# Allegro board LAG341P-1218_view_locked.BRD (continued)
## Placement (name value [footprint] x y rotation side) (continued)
PR805  -  [R_0402]  108.51 133.57 270 bottom
PR806  -  [R_0402]  109.4 133.57 270 bottom
PR807  -  [R_0402]  108.46 131.84 180 bottom
PR808  -  [R_0402]  110.21 132.73 0 bottom
PR809  -  [R_0402]  102.67 129.35 90 bottom
PR818  -  [R_0402]  109.91 128.34 90 bottom
PR819  -  [R_0402]  101.9 130.27 270 bottom
PR838  -  [R0402_0OHM]  105 130.32 0 top
PR839  -  [R_0402]  105 128.8 0 top
PR840  -  [R_0402]  103.56 130.14 270 top
PR841  -  [R0402_0OHM]  105 129.56 0 top
PR900  -  [R0402_0OHM]  237.74 183.28 180 top
PR901  -  [R_1206]  230.37 182.26 0 top
PR902  -  [R0402_0OHM]  243.89 180.31 270 bottom
PR903  -  [R0402_0OHM]  243.13 178.66 270 bottom
PR904  -  [R_0402]  238.18 177.74 90 top
PR905  -  [R_0402]  243.13 180.31 270 bottom
PR906  -  [R_0402]  241.3 178.66 270 bottom
PR907  -  [R_0402]  243.89 177.74 90 bottom
PR908  -  [R_0402]  239.01 178.66 270 bottom
PR909  -  [R_0402]  240.54 177.74 90 bottom
PR910  -  [R0402_0OHM]  239.78 178.66 270 bottom
PR951  -  [R_0402]  244.91 182.65 180 top
PR952  -  [R0402_0OHM]  242.34 182.65 0 top
PR1000  -  [R_0402]  162 183.78 0 bottom
PR1001  -  [R_0402]  162.6 182.98 180 bottom
PR1002  -  [R_0402]  162.9 183.09 180 top
PR1003  -  [R0402_0OHM]  162.09 184.56 0 bottom
PR1004  -  [R_0402]  162.31 181.52 180 bottom
PR1005  -  [R_0402]  167.39 185.27 90 bottom
PR1006  -  [R_0402]  164.05 185.32 90 bottom
PR1007  -  [R_0402]  163.28 186.24 270 bottom
PR1008  -  [R_0402]  164.81 185.32 90 bottom
PR1009  -  [R_1206]  188.77 191.58 180 top
PR1010  -  [R_0603]  161.72 180.61 270 bottom
PR1011  -  [R_0402]  160.96 187.55 270 top
PR1012  -  [R_0603]  163.36 196.31 270 bottom
PR1013  -  [R_0402]  168.24 186.11 270 bottom
PR1014  -  [R_0402]  170.81 185.37 180 bottom
PR1015  -  [R_0603]  168.12 184.57 90 top
PR1016  -  [R_0402]  176.79 177.06 180 top
PR1017  -  [R0402_0OHM]  169.68 179.94 0 bottom
PR1018  -  [R0402_0OHM]  170.47 183.9 180 bottom
PR1019  -  [R_0402]  169.68 180.7 0 bottom
PR1020  -  [R_1206]  172.75 180.79 90 top
PR1021  -  [R0402_0OHM]  170.47 183.14 180 bottom
PR1022  -  [R_0402]  169.68 181.46 0 bottom
PR1023  -  [R_0402]  176.79 177.82 180 top
PR1100  -  [R_0402]  112.01 167.15 180 top
PR1101  -  [R_0603]  111.18 166.07 270 bottom
PR1103  -  [R_0402]  113.84 167.71 90 top
PR1104  -  [R_0402]  105.84 167.84 90 top
PR1105  -  [R_0402]  106.73 168.75 270 top
PR1106  -  [R_0402]  107.75 167.84 90 top
PR1107  -  [R_0402]  108.64 167.84 90 top
PR1108  -  [R0402_0OHM]  118.03 168.37 270 top
PR1109  -  [R_0402]  116.2 168.42 180 top
PR1110  -  [R0402_0OHM]  118.03 169.23 90 top
PR1111  -  [R_0402]  116.2 169.31 180 top
PR1112  -  [R_0402]  109.88 173.18 270 bottom
PR1113  -  [R_0402]  106.22 171.04 270 top
PR1115  -  [R_0402]  117.02 169.23 90 top
PR1116  -  [R_0402]  108.89 171.04 270 top
PR1117  -  [R_0402]  110.67 169.36 90 top
PR1118  -  [R0402_0OHM]  108 171.04 270 top
PR1119  -  [R_0402]  111.66 173.18 270 bottom
PR1120  -  [R_0402]  107.11 171.04 270 top
PR1122  -  [R_0402]  115.19 172.57 270 bottom
PR1123  -  [R_0402]  109.05 172.27 90 bottom
PR1124  -  [R0402_0OHM]  118.24 171.09 180 top
PR1125  -  [R0402_0OHM]  109.78 170.53 270 top
PR1126  -  [R0402_0OHM]  118.24 171.98 180 top
PR1127  -  [R_0402]  117.22 172.87 180 top
PR1130  -  [R0402_0OHM]  105.28 171.85 180 bottom
PR1131  -  [R_0402]  105.28 174.52 180 bottom
PR1132  -  [R0402_0OHM]  103.43 173.45 270 bottom
PR1134  -  [R_0402]  118.8 174.72 270 top
PR1135  -  [R_0402]  113.64 174.77 0 bottom
PR1136  -  [R_0402]  117.96 175.53 0 top
PR1137  -  [R_0402]  118.03 174.72 270 top
PR1138  -  [R_0402]  105.21 172.94 270 top
PR1139  -  [R_0402]  106.53 175.28 0 bottom
PR1140  -  [R_0402]  104.37 173.75 0 top
PR1141  -  [R_0402]  104.27 174.52 180 top
PR1142  -  [R_0402]  117.09 175.66 180 top
PR1143  -  [R_0402]  105.14 176.28 180 top
PR1144  -  [R_0402]  119.18 176.47 90 top
PR1145  -  [R_0402]  103.43 176.22 90 top
PR1146  -  [R_0402]  106.86 181.2 270 top
PR1147  -  [R_0603]  120.38 179.6 180 bottom
PR1148  -  [R_0402]  118.36 178.2 180 top
PR1149  -  [R_0402]  103.43 177.87 90 top
PR1150  -  [R_0603]  120.38 178.33 180 bottom
PR1151  -  [R_0603]  102.92 180.04 90 top
PR1152  -  [R_0603]  120.76 175.79 180 bottom
PR1153  -  [R_0402]  106.05 181.76 180 top
PR1154  -  [R_0402]  115.32 181.76 180 top
PR1155  -  [R_0603]  120.76 177.06 180 bottom
PR1156  -  [R_0603]  111.18 182.83 270 top
PR1157  -  [R_0402]  106.73 179.67 270 bottom
PR1158  -  [R_0402]  107.62 179.67 270 bottom
PR1159  -  [R_0402]  120.4 180.61 180 bottom
PR1160  -  [R_0402]  116.51 179.39 90 bottom
PR1161  -  [R_0402]  112.45 180.69 270 bottom
PR1162  -  [R_0402]  111.18 179.67 270 bottom
PR1163  -  [R_0402]  110.29 179.67 270 bottom
PR1164  -  [R_0402]  109.4 179.67 270 bottom
PR1165  -  [R_0402]  108.51 179.67 270 bottom
PR1166  -  [R_0402]  103.94 180.66 90 top
PR1167  -  [R_0402]  120.4 181.5 180 bottom
PR1168  -  [R_0402]  113.26 181.25 0 bottom
PR1169  -  [R_0402]  119.76 174.77 180 bottom
PR1170  -  [R_0402]  114.55 177.31 180 bottom
PR1171  -  [R_0402]  120.27 178.2 180 top
PR1172  -  [R0402_0OHM]  116.43 180.36 0 top
PR1173  -  [R0402_0OHM]  106.86 185.11 90 top
PR1174  -  [R_0402]  105.13 183.53 0 top
PR1175  -  [R_0402]  117.35 179.47 180 top
PR1176  -  [R_0402]  106.05 186.07 180 top
PR1200  -  [R_0603]  129.84 185.5 90 top
PR1201  -  [R_0603]  130.73 186.2 0 bottom
PR1202  -  [R_0402]  134.49 172.99 180 top
PR1203  -  [R_1206]  135.37 177.95 0 top
PR1204  -  [R_0603]  139.24 187.41 270 bottom
PR1205  -  [R_0603]  141.78 186.01 90 bottom
PR1206  -  [R_0402]  142.11 172.61 180 top
PR1207  -  [R_1206]  142.99 177.95 0 top
PR1251  -  [R_0603]  147.37 187.28 270 bottom
PR1252  -  [R_0603]  150.04 185.82 90 bottom
PR1253  -  [R_0402]  149.73 172.61 180 top
PR1254  -  [R_1206]  150.61 177.69 0 top
PR1255  -  [R_0603]  154.86 187.28 270 bottom
PR1256  -  [R_0603]  157.47 185.82 90 bottom
PR1257  -  [R_0402]  157.35 172.61 180 top
PR1258  -  [R_1206]  157.91 177.37 90 top
PR1500  -  [R_0402]  185.06 179.02 90 bottom
PR1501  -  [R_0402]  185.82 179.93 270 bottom
PR1502  -  [R_0402]  186.59 179.93 270 bottom
PR1503  -  [R0402_0OHM]  183.33 179.86 0 bottom
PR1505  -  [R_0402]  183.14 184.33 180 bottom
PR1507  -  [R_0402]  182.9 181.38 0 bottom
PR1508  -  [R_0402]  182.96 182.17 180 top
PR1509  -  [R_0402]  183.11 181.25 0 top
PR1510  -  [R_0603]  187.72 178.92 0 bottom
PR1511  -  [R_0402]  184.76 182.26 0 top
PR1512  -  [R_1206]  187.95 168.61 90 top
PR1513  -  [R_0603]  191.5 186.07 180 bottom
PR1514  -  [R_0402]  180.46 184.73 0 bottom
PR1515  -  [R_0402]  182.23 185.09 0 bottom
PR1516  -  [R_0402]  182.23 185.85 0 bottom
PR1517  -  [R0402_0OHM]  204.33 122.71 270 bottom
PR1518  -  [R0402_0OHM]  187.55 187.47 0 bottom
PR1519  -  [R_0402]  186.8 185.81 90 bottom
PR1520  -  [R0402_0OHM]  205.28 122.71 270 bottom
PR1521  -  [R_0402]  183.46 186.71 0 bottom
PR1522  -  [R_0402]  187.68 185.82 0 bottom
PR1600  -  [R0402_0OHM]  240.74 170.81 270 bottom
PR1601  -  [R_1206]  239.06 168.74 270 bottom
PR1602  -  [R0402_0OHM]  247.52 174.64 180 bottom
PR1603  -  [R_0402]  246.56 167.21 0 bottom
PR1604  -  [R_0402]  246.61 173.88 0 bottom
PR1605  -  [R_0402]  247.53 169.03 270 bottom
PR1606  -  [R_0402]  247.27 171.35 180 bottom
PR1607  -  [R0402_0OHM]  246.35 170.59 0 bottom
PR1608  -  [R_0402]  246.3 169.82 0 bottom
PR1643  -  [R_0402]  245.67 173.17 90 top
PR1651  -  [R0402_0OHM]  246.43 174.08 270 top
PR1700  -  [R_0603]  111.43 135.84 270 bottom
PR1701  -  [R_0603]  108.64 135.84 270 bottom
PR1702  -  [R_0402]  109.27 147.77 90 top
PR1703  -  [R_1206]  106.29 144.54 180 top
PR1704  -  [R_0603]  102.67 162.13 90 bottom
PR1705  -  [R_0603]  106.73 163.91 90 bottom
PR1706  -  [R_1206]  107.18 155.72 0 top
PR1800  -  [R_0402]  176.62 81.4 180 top
PR1801  -  [R0402_0OHM]  179.37 75.84 180 top
PR1803  -  [R_0402]  178.51 82.42 180 top
PR1804  -  [R_0402]  176.71 83.3 270 top
PR1805  -  [R_0603]  179.13 84.41 180 top
PR1851  -  [R0402_0OHM]  176.61 80.54 180 top
PR1900  -  [R_1206_4P-D]  54.91 78.52 270 bottom
PR1901  -  [R_0603]  47.42 75.27 90 top
PR1902  -  [R_0603]  44.37 75.39 90 top
PR1903  -  [R0603_0OHM]  49.9 76.6 180 top
PR1904  -  [R_0402]  52.88 79.32 90 bottom
PR1905  -  [R_0603]  43.1 75.39 90 top
PR1906  -  [R_0402]  52.12 80.23 270 bottom
PR1907  -  [R_0805]  51.61 80.23 0 top
PR1908  -  [R_0402]  40.39 77.74 180 top
PR1909  -  [R0402_0OHM]  52.64 82.38 180 top
PR1910  -  [R_1206_4P-D]  29.21 90.95 180 bottom
PR1911  -  [R_0402]  53.53 87.46 180 top
PR1912  -  [R_0402]  50.9 81.55 90 top
PR1913  -  [R0402_0OHM]  52.64 83.2 180 top
PR1914  -  [R_0603]  39.87 80.41 0 top
PR1915  -  [R_1206]  38.28 71.65 180 top
PR1916  -  [R_1206]  34.02 81.23 180 top
PR1917  -  [R0402_0OHM]  52.64 83.97 180 top
PR1918  -  [R_0402]  52.88 88.65 90 top
PR1919  -  [R0402_0OHM]  52.64 84.73 180 top
PR1920  -  [R_0402]  54.53 90.91 180 top
PR1921  -  [R0402_0OHM]  52.64 85.49 180 top
PR1922  -  [R0402_0OHM]  41.11 82.32 0 top
PR1923  -  [R_0402]  50.46 87.33 0 top
PR1924  -  [R_0402]  49.64 87.34 270 top
PR1925  -  [R_0402]  47.36 86.43 90 top
PR1926  -  [R_0402]  48.88 87.34 270 top
PR1927  -  [R_0402]  45.35 85.65 180 top
PR1928  -  [R0402_0OHM]  48.12 87.34 270 top
PR1929  -  [R0402_0OHM]  41.33 87.14 90 top
PR1930  -  [R0402_0OHM]  45.59 86.44 0 top
PR1931  -  [R_0402]  40.13 83.46 180 top
PR1932  -  [R0402_0OHM]  43.87 87.19 90 top
PR1933  -  [R0402_0OHM]  44.69 87.19 90 top
PR1934  -  [R_0402]  42.15 87.19 90 top
PR1935  -  [R_0402]  40.13 84.22 180 top
PR1936  -  [R_0402]  58.98 80.79 90 top
PR1937  -  [R0402_0OHM]  61.16 75.54 0 top
PR1938  -  [R_0402]  39.54 87.9 0 top
PR1939  -  [R0402_0OHM]  59 75.66 0 top
PR1940  -  [R0402_0OHM]  61.44 83.08 0 top
PR1941  -  [R0402_0OHM]  62.19 78.99 180 top
PR1942  -  [R_0402]  62.34 82.33 270 top
PR1943  -  [R_0402]  62.13 77.46 270 top
PR1950  -  [R0402_0OHM]  135.65 68.24 180 bottom
PT201  -  [TPC12]  174.6 79.74 0 top
PT202  -  [TPC12]  22.42 76.66 0 top
PU200  -  [LM393DGKR_VSSOP8]  28.52 69.82 180 top
PU201  -  [TC7SH08FU_SSOP5]  15.86 100.36 270 bottom
PU202  -  [TC7SH08FU_SSOP5]  20.23 84.29 0 top
PU203  -  [LM393DGKR_VSSOP8]  21.02 73.85 180 top
PU204  -  [RT9069-33GB_SOT23-5]  65.96 94.76 315 top
PU400  -  [TPS51285BRUKR_QFN20_3X3]  343.71 86.7 180 top
PU500  -  [SY8288RAC_QFN20_3X3]  130.41 75.14 270 bottom
PU600  -  [G5616ARZ1U_TQFN20_3X3]  285.23 98.32 0 bottom
PU700  -  [RT8812AGQW_WQFN20_3X3-S]  193.24 182.86 90 top
PU800  -  [NB681AGD-Z_QFN13_2X3-SVR]  105.98 130.24 270 bottom
PU900  -  [SY8286RAC_QFN20_3X3]  238.42 183.18 270 bottom
PU1001  -  [RT8816AGQW_WQFN20_3X3]  164.34 181.55 90 bottom
PU1100  -  [NCP81215MNTXG_QFN52_6X6]  113.49 173.51 180 top
PU1200  -  [NCP302035MNTXG_PQFN33_5X5]  129.75 184.79 0 bottom
PU1201  -  [NCP302035MNTXG_PQFN33_5X5]  138.76 184.79 0 bottom
PU1251  -  [NCP302035MNTXG_PQFN33_5X5]  147.65 184.6 0 bottom
PU1252  -  [NCP302035MNTXG_PQFN33_5X5]  155.08 184.6 0 bottom
PU1501  -  [RT8816AGQW_WQFN20_3X3]  187.46 181.43 180 bottom
PU1600  -  [SY8286RAC_QFN20_3X3]  241.99 170.54 0 bottom
PU1700  -  [NCP302035MNTXG_PQFN33_5X5]  109.5 137.44 180 bottom
PU1701  -  [NCP302035MNTXG_PQFN33_5X5]  104.85 162.69 0 bottom
PU1800  -  [RT9059GQW_WDFN10_3X3]  179.79 81.06 180 top
PU1900  -  [ISL88738HRTZ-T_TQFN32_4X4]  44.63 83.2 0 top
PU1901  -  [TC7SH08FU_SSOP5]  60.04 80.16 0 top
Q4  -  [L2N7002WT1G_SC-70-3]  339.27 170.51 0 top
Q5  -  [DMN66D0LDW-7_SOT363-6]  272.79 93 270 top
Q6  -  [L2N7002WT1G_SC-70-3]  308.66 102.44 180 bottom
QE2  -  [DMN65D8LDW-7_SOT363-6]  193.98 78.02 0 top
QE4  -  [DMN65D8LDW-7_SOT363-6]  284.72 70.49 90 top
QE5  -  [MMBT3904WH_SOT323-3]  172.56 184.34 0 bottom
QE6  -  [MMBT3904WH_SOT323-3]  187.17 118.16 0 top
QE7  -  [MMBT3904WH_SOT323-3]  110.63 182.9 270 bottom
QE8  -  [MMBT3904WH_SOT323-3]  177.59 116.73 180 bottom
QE9  -  [MMBT3904WH_SOT323-3]  238.87 174.57 0 bottom
QE10  -  [MMBT3904WH_SOT323-3]  298.18 71.81 0 top
QE11  -  [MMBT3904WH_SOT323-3]  27.36 115.93 90 bottom
QE12  -  [MMBT3904WH_SOT323-3]  279.2 95.31 180 bottom
QE13  -  [L2N7002WT1G_SC-70-3]  186.31 74.4 180 top
QE15  -  [MMBT3904WH_SOT323-3]  156.43 136.53 180 top
QE18  -  [DMN65D8LDW-7_SOT363-6]  284.72 73.41 90 top
QE20  -  [L2N7002WT1G_SC-70-3]  136.89 81.17 270 top
QF1  -  [DMN65D8LDW-7_SOT363-6]  231.76 110.9 270 top
QH1  -  [LP2301ALT1G_SOT23-3]  139.62 79.14 0 top
QH3  -  [2N7002KDW_SOT363-6]  345.99 150.85 0 top
QH4  -  [DMN65D8LDW-7_SOT363-6]  108.19 77.5 270 bottom
QH5  -  [2N7002KDW_SOT363-6]  344.78 153.02 180 top
QI10  -  [L2N7002WT1G_SC-70-3]  324.66 111.34 180 top
QR1  -  [L2N7002WT1G_SC-70-3]  346 99.39 180 bottom
QR104  -  [L2N7002WT1G_SC-70-3]  174.68 76.47 0 top
QR105  -  [L2N7002WT1G_SC-70-3]  331.01 109.43 0 bottom
QRTC  -  [LP2301ALT1G_SOT23-3]  169.21 73.55 270 top
QRTC1  -  [DMN65D8LW-7_SOT323-3]  176.46 71.22 90 top
QV3  -  [DMN65D8LDW-7_SOT363-6]  246.86 113.69 0 top
QV11  -  [SI3457BDV-T1-E3_TSOP6]  43.85 101.18 180 top
QV12  -  [L2N7002WT1G_SC-70-3]  37.07 100.83 270 top
QV21  -  [DMN63D8LDW-7_SOT363-6]  199.51 112.96 180 top
QV89  -  [L2N7002WT1G_SC-70-3]  24.18 118.83 180 top
QV91  -  [2N7002W-T-R7_SOT323-3]  214.41 109.91 270 top
QV98  -  [2N7002W-T-R7_SOT323-3]  241.83 116.24 180 top
QV101  -  [2N7002W-T-R7_SOT323-3]  217.89 173.93 90 top
QV102  -  [2N7002W-T-R7_SOT323-3]  242.49 160.19 90 top
QV103  -  [2N7002W-T-R7_SOT323-3]  196.39 116.44 0 top
QV105  -  [2N7002W-T-R7_SOT323-3]  227.71 111.04 180 top
QZ6  -  [DMN65D8LDW-7_SOT363-6]  249.34 120.23 0 top
QZ9  -  [DMG2301U-7_SOT23-3]  51.87 92.63 0 bottom
QZ14  -  [DMN65D8LDW-7_SOT363-6]  220.95 184.93 90 top
QZ15  -  [DMN65D8LDW-7_SOT363-6]  164.35 184.09 0 top
QZ17  -  [DMN65D8LDW-7_SOT363-6]  249.86 109.75 0 top
QZ18  -  [L2N7002WT1G_SC-70-3]  219.38 180.3 180 top
R3  -  [R_0402]  170.6 71.01 0 top
R276  -  [R_0201]  168.22 72.01 270 top
R277  -  [R_0201]  172.85 73.42 270 top
R281  -  [R_0603]  312.98 98.38 270 bottom
R5831  -  [R_0402]  310.11 86.76 0 top
R5832  -  [R_0402]  143.05 81.7 180 top
R5841  -  [R_0201]  317.68 104.58 270 bottom
R5842  -  [R_0402]  276.61 92.6 180 top
R5843  -  [R_0402]  271.83 91.64 90 top
RA2  -  [R0603_0OHM]  0.67 97.91 90 top
RA4  -  [R_0201]  0.58 95.26 180 top
RA6  -  [R_0201]  0.18 96.75 90 bottom
RA7  -  [R_0201]  0.58 94.67 180 top
RA12  -  [R_0201]  13.49 103.46 180 bottom
RA13  -  [R_0201]  4.84 99.93 0 bottom
RA14  -  [R_0201]  4.84 100.56 0 bottom
RA15  -  [R_0201]  8.94 99.85 90 bottom
RA16  -  [R_0201]  7.86 99.8 90 bottom
RA17  -  [R_0201]  1.8 95.74 90 bottom
RA18  -  [R0603_0OHM]  2.41 97.06 270 top
RA19  -  [R_0402]  7.75 112.1 180 top
RA20  -  [R_0402]  9.73 125.81 0 bottom
RA21  -  [R_0402]  8.38 125.81 180 bottom
RA27  -  [R_0402]  9.72 108.67 180 top
RA28  -  [R_0402]  11.62 112.03 180 top
RA29  -  [R_0402]  9.19 110.46 270 top
RA30  -  [R_0402]  7.86 110.46 270 top
RA31  -  [R_0402]  7.15 108.67 0 top
RA51  -  [R_0402]  11.92 116.12 0 top
RA52  -  [R_0402]  11.65 114.94 90 bottom
RA57  -  [R_0201]  0 95.83 0 top
RA68  -  [R_0201]  11.66 103.92 315 bottom
RA73  -  [R_0603]  3.15 106.77 0 top
RA74  -  [R0603_0OHM]  9.93 107.76 270 top
RA75  -  [R_0402]  8.52 112.12 0 top
RA82  -  [R_0201]  2.73 111.94 180 bottom
RA93  -  [R_0402]  2.34 97.1 90 bottom
RA94  -  [R0402_0OHM]  0.13 98.37 90 bottom
RA95  -  [R_0402]  0.69 126.48 270 bottom
RA96  -  [R_0201]  99.87 84.35 180 top
RA97  -  [R_0201]  99.87 84.93 180 top
RA98  -  [R_0201]  20.5 99.71 270 bottom
RA99  -  [R_0201]  20.5 97.86 90 bottom
RA100  -  [R_0402]  5.62 99.55 90 top
RA101  -  [R_0402]  7.51 99.97 180 top
RA102  -  [R_0402]  148.94 74.24 270 bottom
RA103  -  [R_0402]  145.99 76.15 270 bottom
RC183  -  [R_0402]  339.08 109.1 90 bottom
RC184  -  [R_0402]  339.9 109.1 90 bottom
RC5831  -  [R_0201]  111.48 75.96 0 top
RC5832  -  [R_0201]  111.43 77.62 0 top
RC5833  -  [R_0201]  111.48 78.38 0 top
RC5834  -  [R_0201]  111.48 76.73 0 top
RC5835  -  [R_0402]  343.13 112.51 270 bottom
RD1  -  [R_0402]  169.1 86.97 0 top
RD2  -  [R_0402]  171.37 92.36 0 top
RD3  -  [R_0402]  150.22 85.01 180 top
RD4  -  [R_0402]  246.57 86 90 top
RD5  -  [R0402_0OHM]  246.58 84.23 0 top
RD6  -  [R_0402]  226.06 83.56 180 top
RD7  -  [R_0402]  266.24 80.08 180 top
RD8  -  [R_0402]  265.28 76.47 0 top
RD9  -  [R_0402]  266.19 73.55 180 top
RD10  -  [R_0402]  254.04 71.14 0 bottom
RD28  -  [R0402_0OHM]  170.01 86.08 180 top
RD29  -  [R0402_0OHM]  173.88 91.41 0 top
RD30  -  [R0402_0OHM]  148.96 85.84 90 top
RD31  -  [R0402_0OHM]  132.09 84.22 0 top
RD35  -  [R_0402]  134.67 84.22 180 top
RD38  -  [R0402_0OHM]  245.48 86.24 180 top
RD39  -  [R_0402]  247.48 83.42 180 top
RD40  -  [R0402_0OHM]  225.15 84.37 0 top
RD58  -  [R0402_0OHM]  252.26 71.14 0 bottom
RD59  -  [R_0402]  265.28 75.52 0 top
RD100  -  [R_0402]  235.69 75.84 0 top
RD101  -  [R_0402]  265.4 87.65 0 top
RE3  -  [R_0402]  330.25 174.71 90 top
RE7  -  [R_0402]  189.42 78.25 180 top
RE9  -  [R_0402]  195.18 81.24 180 top
RE16  -  [R0603_0OHM]  279.27 83.32 0 top
RE19  -  [R_0402]  304.09 90.44 0 top
RE20  -  [R_0402]  293.8 92.47 90 top
RE21  -  [R_0402]  293.17 89.55 0 top
RE22  -  [R_0402]  304.27 77.74 0 top
RE23  -  [R_0402]  304.27 76.85 0 top
RE24  -  [R_0402]  191.82 81.04 180 bottom
RE25  -  [R_0402]  288.47 88.79 180 top
RE26  -  [R_0402]  189.15 81.04 0 bottom
RE27  -  [R_0402]  301.32 95.14 270 top
RE30  -  [R_0402]  307.19 86.51 0 top
RE31  -  [R_0402]  307.26 69.92 90 top
RE32  -  [R_0402]  308.17 76.98 180 top
RE33  -  [R_0402]  300.79 70.62 90 top
RE34  -  [R_0402]  285.22 82.82 0 top
RE35  -  [R_0402]  300.66 89.93 270 top
RE36  -  [R_0402]  286.13 84.85 180 top
RE38  -  [R_0402]  308.1 87.52 180 top
RE39  -  [R0402_0OHM]  308.1 88.54 180 top
RE41  -  [R_0402]  305.05 87.84 180 top
RE43  -  [R_0402]  291.36 71.65 270 top
RE44  -  [R_0402]  292.25 70.73 90 top
RE45  -  [R_0402]  305.05 87.01 180 top
RE48  -  [R_0402]  301.93 92.02 90 top
RE50  -  [R_0402]  287.83 71.63 0 top
RE51  -  [R0402_0OHM]  289.36 76.78 90 top
RE52  -  [R_0402]  286.51 71.77 180 top
RE54  -  [R_0402]  289.48 71.65 270 top
RE55  -  [R_0402]  308.15 74.44 180 top
RE56  -  [R_0402]  280.86 70.44 0 top
RE58  -  [R_0402]  286.13 86.89 180 top
RE59  -  [R_0402]  296.01 92.47 0 top
RE60  -  [R_0402]  310.95 95.32 90 top
RE61  -  [R_0402]  296.93 90.29 180 top
RE62  -  [R_0402]  292.67 100.16 180 top
RE63  -  [R_0402]  305.49 94.94 90 top
RE64  -  [R_0402]  304.6 94.07 270 top
RE65  -  [R_0402]  304.6 94.94 90 top
RE66  -  [R_0402]  300.38 73.36 90 top
RE67  -  [R_0402]  299.52 89.17 90 top
RE68  -  [R_0402]  298.12 92.98 270 top
RE69  -  [R_0402]  299.9 70.62 90 top
RE70  -  [R_0402]  299.01 92.98 270 top
RE71  -  [R_0402]  301.55 90.01 270 top
RE72  -  [R_0402]  293.81 73.44 90 top
RE81  -  [R_0201]  98.48 103.18 270 top
RE82  -  [R_0201]  95.72 101.25 90 top
RE83  -  [R_0201]  332 114.33 90 bottom
RE84  -  [R_0201]  334.45 116.27 0 bottom
RE86  -  [R_0201]  152.07 80.32 270 top
RE87  -  [R_0402]  186.77 77.44 180 top
RE89  -  [R_0402]  283.58 80.59 90 top
RE90  -  [R_0402]  281.85 80.6 0 top
RE94  -  [R_0402]  281.74 73.47 90 top
RE95  -  [R_0402]  284.73 75.9 180 top
RE96  -  [R_0402]  297.79 89.12 90 top
RE99  -  [R_0402]  294.94 89.1 90 top
RE100  -  [R_0201]  95.85 100.14 0 top
RE101  -  [R_0201]  331.91 117.92 0 bottom
RE104  -  [R0603_0OHM]  94.79 101.26 90 top
RE105  -  [R0603_0OHM]  333.48 116.26 90 bottom
RE108  -  [R0402_0OHM]  79.1 102.11 0 top
RE109  -  [R0402_0OHM]  79.1 102.88 0 top
RE110  -  [R_0402]  286.13 83.84 180 top
RE111  -  [R_0402]  307.26 80.28 0 top
RE112  -  [R0402_0OHM]  310.11 85.49 0 top
RE113  -  [R_0201]  147.1 70.88 0 top
RE114  -  [R_0201]  146.66 74.06 0 top
RE115  -  [R_0201]  146.41 76.73 0 top
RE116  -  [R0402_0OHM]  150.42 77.62 0 bottom
RE117  -  [R0402_0OHM]  150.42 76.73 0 bottom
RE122  -  [R0402_0OHM]  305.18 75.84 180 top
RE125  -  [R_0201]  153.16 70.12 180 top
RE126  -  [R_0402]  307.25 77.81 0 top
RE129  -  [R0603_0OHM]  157.34 78.5 180 top
RE133  -  [R0201_0OHM]  146.66 75.08 0 top
RE136  -  [R_0402]  281.74 75.84 0 top
RE137  -  [R_0402]  285.93 74.39 270 top
RE138  -  [R0402_0OHM]  186.3 72.67 270 top
RE139  -  [R0402_0OHM]  308.15 78.76 180 top
RE141  -  [R0603_0OHM]  149.81 72.19 0 bottom
RE142  -  [R_0402]  304.52 82.57 0 top
RE143  -  [R_0402]  175.44 73.55 180 top
RE145  -  [R_0402]  292.28 73.53 90 top
RE183  -  [R_0402]  303.52 74.39 270 top
RE255  -  [R_0402]  316.15 97.6 90 bottom
RE273  -  [R_0402]  318.95 98.37 90 bottom
RE274  -  [R_0402]  317.55 98.37 90 bottom
RE275  -  [R_0402]  329.23 110.97 270 bottom
RE283  -  [R_0402]  293.83 71.65 270 top
RE284  -  [R_0402]  293.04 71.65 270 top
RE285  -  [R_0402]  304.14 84.47 0 top
RE286  -  [R_0402]  304.22 78.63 0 top
RE287  -  [R0402_0OHM]  299.65 95.12 0 top
RE288  -  [R0402_0OHM]  300.16 95.95 0 top
RE290  -  [R_0402]  304.98 88.92 180 top
RE291  -  [R_0402]  100 74.44 180 bottom
RE292  -  [R_0402]  299.79 92.06 90 top
RE293  -  [R_0402]  290.75 74.44 270 top
RE294  -  [R_0402]  291.52 74.44 270 top
RE295  -  [R_0402]  287.05 80.13 90 top
RE296  -  [R_0402]  288.09 82.31 180 top
RE297  -  [R_0402]  304.19 92.22 0 top
RE298  -  [R_0402]  300.28 96.79 0 top
RE299  -  [R_0402]  301.94 96.89 270 top
RE300  -  [R_0402]  308.18 79.52 180 top
RE301  -  [R_0402]  276.25 79.01 90 top
RE303  -  [R_0402]  301.59 70.61 90 top
RE304  -  [R_0603]  279.2 79.55 0 top
RE305  -  [R0402_0OHM]  307.26 92.09 0 top
RE306  -  [R_0402]  307.22 91.3 0 top
RE307  -  [R_0402]  267.16 87.66 0 top
RE309  -  [R_0402]  150.28 75.3 0 bottom
RE310  -  [R_0402]  150.44 78.4 0 bottom
RE311  -  [R_0402]  293.05 73.53 90 top
RE313  -  [R0201_0OHM]  291.95 99.62 270 bottom
RE321  -  [R_0201]  88.02 81.07 270 top
RE322  -  [R_0402]  303.64 94.37 90 bottom
RE323  -  [R_0402]  303.64 96.14 90 bottom
RF1  -  [R0603_0OHM]  239.42 111.66 90 top
RF2  -  [R_0402]  230.7 110.64 270 top
RF3  -  [R_0402]  236.21 111.6 270 top
RF4  -  [R_0402]  236.11 112.92 180 top
RF5  -  [R_0402]  237.1 111.6 270 top
RH2  -  [R_0201]  74.21 68.92 90 top
RH5  -  [R_0402]  120.95 161.36 90 bottom
RH6  -  [R_0402]  74.57 71.32 90 top
RH8  -  [R0402_0OHM]  122.78 163.21 0 bottom
RH12  -  [R0402_0OHM]  116.95 162.59 270 bottom
RH24  -  [R_0201]  171.57 123.2 0 bottom
RH30  -  [R_0402]  174.82 153.53 90 top
RH42  -  [R_0402]  77.75 84.82 180 top
RH59  -  [R_0201]  132.54 141.81 0 bottom
RH67  -  [R_0402]  277.22 73.72 180 top
RH70  -  [R_0402]  68.12 72.28 0 bottom
RH71  -  [R_0402]  100.08 84.85 180 bottom
RH72  -  [R_0201]  100.51 84.35 90 top
RH74  -  [R_0201]  68.76 75.84 0 bottom
RH75  -  [R_0201]  71.11 78.92 270 top
RH77  -  [R_0402]  61.79 68.92 180 bottom
RH78  -  [R_0201]  64.59 76.35 0 top
RH82  -  [R_0402]  64.25 69.68 0 top
RH83  -  [R_0201]  68.68 72.28 0 top
RH84  -  [R_0201]  72.69 68.56 90 top
RH85  -  [R_0402]  81.71 76.14 90 top
RH91  -  [R_0201]  100.71 76.5 180 bottom
RH95  -  [R_0402]  100.46 78.48 180 bottom
RH96  -  [R0201_0OHM]  91.63 69.13 180 top
RH97  -  [R_0402]  117.1 159.11 0 bottom
RH98  -  [R_0402]  116.93 159.97 90 bottom
RH100  -  [R_0402]  116.09 160 90 bottom
RH108  -  [R_0201]  90.68 95.47 225 top
RH109  -  [R_0402]  99.85 90.75 0 bottom
RH110  -  [R_0201]  87.64 68.09 0 bottom
RH119  -  [R_0402]  106.1 70.81 90 top
RH120  -  [R_0402]  105.21 70.81 90 top
RH130  -  [R_0402]  83.81 74.81 180 top
RH133  -  [R0402_0OHM]  68.66 74.24 0 bottom
RH145  -  [R_0402]  178.42 147.41 315 bottom
RH146  -  [R_0201]  100.08 77.82 180 bottom
RH147  -  [R_0201]  103.09 77.79 180 bottom
RH148  -  [R_0201]  171.57 123.77 0 bottom
RH149  -  [R_0201]  171.57 124.36 0 bottom
RH150  -  [R_0201]  169.34 122.7 0 bottom
RH151  -  [R_0402]  133.32 166.26 0 top
RH152  -  [R_0402]  133.32 167.02 0 top
RH153  -  [R_0402]  134.98 166.26 0 top
RH154  -  [R_0402]  178.28 129.88 270 top
RH155  -  [R_0402]  128.04 149.88 0 bottom
RH156  -  [R_0201]  126.12 146.45 0 bottom
RH158  -  [R_0201]  127.91 148.04 0 bottom
RH163  -  [R_0402]  170.27 147.76 90 top
RH164  -  [R_0402]  179.11 128.96 90 top
RH165  -  [R_0201]  125.23 147.97 0 bottom
RH167  -  [R_0402]  177.34 128.95 90 top
RH168  -  [R_0201]  79.44 73.07 270 top
RH183  -  [R_0402]  129.69 144.48 90 top
RH184  -  [R_0402]  130.56 144.48 90 top
RH185  -  [R_0402]  131.66 141.98 180 top
RH186  -  [R_0402]  128.45 138.88 90 top
RH187  -  [R_0402]  129.84 141.06 90 top
RH188  -  [R_0402]  129.84 139.26 90 top
RH189  -  [R_0402]  99.46 82.44 0 bottom
RH190  -  [R0402_0OHM]  130.86 150.82 90 bottom
RH191  -  [R_0402]  100.2 83.71 0 bottom
RH192  -  [R_0402]  189.48 128.9 90 top
RH197  -  [R_0402]  139.17 162.07 180 bottom
RH198  -  [R0402_0OHM]  137.49 162.05 90 bottom
RH200  -  [R_0201]  131.62 151.57 270 bottom
RH201  -  [R_0402]  125.07 168.93 0 bottom
RH202  -  [R0402_0OHM]  123.7 168.93 180 bottom
RH203  -  [R_0402]  131.03 161.92 90 bottom
RH204  -  [R0402_0OHM]  132.58 161.92 90 bottom
RH206  -  [R_0402]  125.17 86.73 270 top
RH207  -  [R_0402]  230.91 87.58 270 top
RH209  -  [R_0402]  124.4 85.82 180 top
RH210  -  [R_0402]  230.91 85.8 270 top
RH211  -  [R_0402]  121.79 85.7 180 top
RH212  -  [R_0402]  229.18 85.61 270 top
RH309  -  [R_0402]  65.25 75.08 0 top
RH383  -  [R_0402]  84.63 77.31 270 top
RH401  -  [R_0201]  65.13 73.12 0 top
RH423  -  [R_0201]  97.21 73.04 180 top
RH428  -  [R_0201]  82.97 72.82 270 top
RH453  -  [R_0402]  69.6 74.06 180 top
RH454  -  [R_0201]  113.51 73.07 180 top
RH456  -  [R_0402]  179.01 153.41 90 bottom
RH458  -  [R_0201]  104.83 76.27 90 bottom
RH459  -  [R_0201]  109.65 75.96 180 bottom
RH460  -  [R_0201]  83.66 69.13 90 top
RH461  -  [R_0201]  84.23 69.17 90 top
RH462  -  [R_0201]  107.52 76.89 270 top
RH463  -  [R_0201]  108.13 76.89 270 top
RH465  -  [R0402_0OHM]  136.71 162.08 90 bottom
RH466  -  [R_0402]  135.9 162.11 90 bottom
RH469  -  [R_0402]  125.07 169.82 0 bottom
RH470  -  [R0402_0OHM]  123.7 169.82 180 bottom
RH471  -  [R0402_0OHM]  131.8 161.92 90 bottom
RH472  -  [R_0402]  133.35 162.83 270 bottom
RH474  -  [R_0402]  127.94 152.16 0 bottom
RH475  -  [R_0402]  126.34 151.5 270 bottom
RH477  -  [R0402_0OHM]  116.07 162.59 270 bottom
RH478  -  [R0402_0OHM]  117.91 162.59 270 bottom
RH479  -  [R_0402]  116.95 161.57 180 top
RH480  -  [R_0402]  116.95 160.69 180 top
RH481  -  [R_0402]  128.23 159.94 270 top
RH482  -  [R_0402]  128.23 157.24 90 top
RH483  -  [R_0402]  128.22 165.4 270 top
RH484  -  [R_0402]  123.48 86.62 0 top
RH485  -  [R_0402]  229.96 87.58 270 top
RH487  -  [R_0201]  114.47 73.09 0 top
RH488  -  [R_0402]  128.23 163.62 270 top
RH489  -  [R_0402]  73.99 76.19 180 top
RH490  -  [R_0402]  125.48 163.21 180 bottom
RH491  -  [R0402_0OHM]  128.91 168.17 180 top
RH492  -  [R_0402]  116.95 162.59 180 top
RH493  -  [R_0402]  71.88 78.92 270 top
RH494  -  [R_0402]  129.46 164.94 270 bottom
RH495  -  [R_0402]  132.38 164.94 270 bottom
RH496  -  [R_0402]  131.43 164.94 270 bottom
RH497  -  [R_0402]  127.91 149.12 0 bottom
RH498  -  [R_0402]  128.91 168.93 180 top
RH501  -  [R_0201]  84.51 72.57 270 top
RH502  -  [R_0201]  84.81 69.17 90 top
RH503  -  [R_0402]  86.16 72.23 270 top
RH504  -  [R_0402]  83.74 72.87 270 top
RH505  -  [R_0402]  85.27 72.48 270 top
RH506  -  [R_0402]  97.1 71.14 0 top
RH508  -  [R_0201]  77.39 81.93 0 top
RH510  -  [R_0402]  69 82.12 180 bottom
RH511  -  [R_0201]  69.58 87.55 90 bottom
RH512  -  [R_0201]  69.06 83.41 180 bottom
RH513  -  [R_0201]  69.06 82.82 180 bottom
RH515  -  [R_0402]  74.6 73.81 180 top
RH516  -  [R_0201]  99.75 75.71 180 top
RH518  -  [R_0402]  106.98 69.47 270 top
RH519  -  [R_0402]  128.07 150.64 0 bottom
RH523  -  [R_0402]  86.7 76.97 270 top
RH524  -  [R_0402]  100.08 73.12 180 top
RH525  -  [R_0402]  119.13 121.43 180 top
RH527  -  [R_0402]  64.5 80.52 90 bottom
RH528  -  [R_0402]  65.58 79.14 180 bottom
RH529  -  [R_0201]  60.93 71.52 0 bottom
RH530  -  [R_0402]  182.5 113.94 180 top
RH531  -  [R_0201]  74.3 74.82 180 top
RH533  -  [R_0402]  76.52 68.84 180 top
RH535  -  [R_0402]  82.85 76.14 90 top
RH536  -  [R_0201]  109.16 72.31 0 top
RH537  -  [R_0402]  256.46 111.65 180 top
RH539  -  [R_0402]  100.37 81.67 180 bottom
RH540  -  [R0402_0OHM]  130.54 164.94 270 bottom
RH541  -  [R0402_0OHM]  133.27 164.94 270 bottom
RH542  -  [R0402_0OHM]  128.32 163.14 90 bottom
RH543  -  [R0402_0OHM]  126.57 148.97 270 bottom
RH544  -  [R_0402]  65.16 71.23 180 top
RH545  -  [R_0201]  74.79 69.5 270 top
RH546  -  [R_0402]  85.52 75.33 180 top
RH547  -  [R_0402]  81.31 69.14 270 bottom
RH548  -  [R_0402]  86.14 68.23 90 bottom
RH549  -  [R_0402]  84 68.23 90 bottom
RH550  -  [R_0402]  82.68 78.25 180 top
RH551  -  [R_0402]  68.41 83.77 0 top
RH552  -  [R_0201]  79.41 81.15 90 top
RH553  -  [R_0201]  74.79 80.55 180 top
RH554  -  [R_0201]  74.35 81.43 180 top
RH555  -  [R_0201]  74.79 79.79 180 top
RH557  -  [R_0402]  64.44 72.92 180 top
RH561  -  [R_0402]  103.34 71.71 180 top
RH562  -  [R_0402]  103.34 72.73 180 top
RH563  -  [R_0402]  100.89 69.11 180 top
RH564  -  [R_0402]  75.11 77.67 90 top
RH565  -  [R_0402]  74.36 78.57 180 top
RH566  -  [R_0402]  106.25 76.22 180 top
RH567  -  [R_0402]  104.5 76.22 180 top
RH568  -  [R_0201]  96.04 74.39 270 top
RH569  -  [R_0201]  96.57 75 0 top
RH570  -  [R_0201]  126.12 147.08 0 bottom
RH571  -  [R_0402]  102.21 77.11 0 bottom
RH572  -  [R_0402]  65.16 70.45 180 top
RH573  -  [R_0402]  68.68 74.95 0 top
RH576  -  [R_0402]  66.13 76.78 270 top
RH577  -  [R0402_0OHM]  68.68 77.62 0 top
RH578  -  [R0402_0OHM]  68.72 76.82 0 top
RH579  -  [R0402_0OHM]  68.69 75.78 0 top
RH580  -  [R0201_0OHM]  99.96 91.81 0 bottom
RH581  -  [R0201_0OHM]  99.96 90.06 0 bottom
RH585  -  [R_0603]  60.27 79.01 180 bottom
RH586  -  [R0201_0OHM]  61.52 70.74 180 bottom
RH590  -  [R_0201]  278.56 73.89 90 top
RH597  -  [R_0402]  117.27 76.66 270 top
RH599  -  [R_0402]  117.73 78.63 180 top
RH1145  -  [R_0201]  85.22 78.58 180 top
RH1146  -  [R_0201]  100.13 77.07 0 bottom
RH1152  -  [R_0201]  304.09 89.68 0 top
RH1943  -  [R_0402]  118.29 76.17 270 top
RH1957  -  [R_0603]  122.4 78.58 180 top
RH1958  -  [R_0402]  127.94 151.4 0 bottom
RH5832  -  [R_0201]  99.87 70.38 0 bottom
RH5833  -  [R_0201]  99.87 71.01 0 bottom
RH5834  -  [R_0201]  99.92 72.54 270 bottom
RH5835  -  [R_0402]  100.13 75.33 180 bottom
RH5836  -  [R_0402]  101.4 81.17 0 bottom
RH5837  -  [R_0402]  79.11 68.26 0 bottom
RH5838  -  [R_0402]  81.08 72.92 270 top
RH5839  -  [R_0201]  80.38 73.07 270 top
RH5840  -  [R_0201]  76.85 77.68 0 top
RH5841  -  [R_0201]  68.5 73.55 0 bottom
RH5842  -  [R_0402]  77.47 68.26 0 bottom
RH5844  -  [R_0201]  77.52 80.41 0 top
RH5845  -  [R_0201]  70.05 79.94 180 bottom
RH5846  -  [R_0201]  70.05 80.52 180 bottom
RH5847  -  [R_0201]  78.2 79.35 0 top
RH5848  -  [R_0201]  69.79 81.09 180 bottom
RH5849  -  [R_0201]  68.59 81.44 180 bottom
RH5850  -  [R_0201]  95.17 86.51 180 top
RH5853  -  [R_0201]  90.65 77.5 270 top
RH5854  -  [R_0201]  91.25 77.08 0 top
RH5855  -  [R_0201]  88.42 79.02 270 top
RH5856  -  [R_0402]  89.74 84.88 270 top
RH5857  -  [R_0201]  89.42 68.09 0 bottom
RH5858  -  [R_0201]  90 68.73 180 bottom
RH5859  -  [R_0402]  66.6 74.31 180 top
RH5860  -  [R_0402]  74.74 76.93 270 top
RH5861  -  [R_0402]  296.93 72.28 180 top
RH5864  -  [R_0402]  142.96 80.91 0 top
RH5865  -  [R_0402]  142.94 80.13 0 top
RH5866  -  [R_0603]  55.6 71.27 90 top
RH5867  -  [R_0402]  133.91 81.76 270 top
RH5868  -  [R_0402]  139.67 82.95 0 top
RH5869  -  [R_0201]  304.44 83.39 180 top
RH5870  -  [R_0201]  244.91 74.95 180 top
RH5871  -  [R_0201]  244.85 74.27 0 top
RH5872  -  [R0201_0OHM]  296.69 70.66 270 top
RH5873  -  [R0201_0OHM]  97.71 72.28 180 top
RH5875  -  [R_0402]  88.84 74.42 90 top
RH5876  -  [R_0402]  90.26 74.92 0 top
RH5879  -  [R_0402]  87.05 81.55 180 top
RH5880  -  [R_0402]  88.32 81.81 0 top
RH5881  -  [R_0201]  76.67 83.2 180 top
RH5882  -  [R_0201]  80.89 76.24 180 top
RH5883  -  [R_0201]  79.18 75.44 90 top
RH5884  -  [R_0402]  288.48 79.71 0 top
RH5889  -  [R_0201]  94.83 68.19 180 top
RH5890  -  [R_0201]  87.85 78.44 90 top
RH5891  -  [R_0201]  339.39 111.87 90 bottom
RH5892  -  [R_0201]  67.12 78.95 180 bottom
RH5893  -  [R_0201]  174.73 178.68 180 top
RH5894  -  [R_0201]  23.51 144.8 0 top
RH5895  -  [R_0201]  67.84 79.55 0 bottom
RI4  -  [R_0402]  20.88 166.06 90 bottom
RI5  -  [R_0402]  20.88 164.15 90 bottom
RI6  -  [R_0402]  25.46 165.97 90 top
RI7  -  [R_0402]  25.41 165.21 270 top
RI8  -  [R_0402]  21.39 169.61 90 bottom
RI9  -  [R_0402]  325.93 126.43 90 bottom
RI10  -  [R_0402]  326.77 126.43 90 bottom
RI11  -  [R_0402]  335.06 129.62 0 bottom
RI12  -  [R_0402]  335.06 128.73 0 bottom
RI13  -  [R_0402]  323.53 116.28 0 top
RI14  -  [R_0805]  325.42 108.44 270 top
RI15  -  [R_0402]  324.03 103.27 0 top
RI16  -  [R_0402]  324.03 101.75 0 top
RI17  -  [R_0402]  317.04 103.78 180 top
RI18  -  [R_0402]  317.04 102.25 180 top
RI19  -  [R_0402]  324.03 102.51 0 top
RI20  -  [R_0402]  324.03 104.03 0 top
RI21  -  [R_0402]  317.04 103.02 180 top
RI22  -  [R_0402]  317.04 100.73 180 top
RI23  -  [R_0402]  318.82 98.82 270 top
RI24  -  [R_0402]  324.03 100.98 0 top
RI25  -  [R0402_0OHM]  318.06 105.94 90 top
RI26  -  [R_0402]  17.2 170.02 270 bottom
RI27  -  [R_0402]  323.35 120.68 90 top
RI28  -  [R_0402]  324.3 117.86 90 top
RI30  -  [R_0402]  323.56 109.42 90 bottom
RI31  -  [R_0402]  328.35 110.05 90 bottom
RI32  -  [R0402_0OHM]  325.93 112.34 90 bottom
RI33  -  [R0402_0OHM]  326.82 112.34 90 bottom
RI34  -  [R_0402]  325.98 111.4 0 bottom
RI35  -  [R_0402]  324.92 109.42 90 bottom
RI36  -  [R_0402]  317.04 101.49 180 top
RI37  -  [R0402_0OHM]  321.74 97.05 270 top
RI38  -  [R0402_0OHM]  322.5 97.05 270 top
RI39  -  [R0402_0OHM]  320.34 98.82 270 top
RI40  -  [R0402_0OHM]  319.58 98.82 270 top
RI45  -  [R0805_0OHM]  325.42 100.86 90 bottom
RI46  -  [R_0402]  321.31 111.4 180 top
RL1  -  [R_0402]  341.99 168.55 0 top
RL2  -  [R_0402]  341.99 169.56 0 top
RL3  -  [R_0402]  341.99 170.58 0 top
RL4  -  [R_0402]  341.99 171.6 0 top
RL5  -  [R_0402]  341.99 172.48 0 top
RM1  -  [R_0402]  24.69 140.48 0 top
RM2  -  [R_0402]  24.69 141.37 0 top
RM3  -  [R_0402]  24.69 136.16 0 top
RM4  -  [R_0402]  18.52 135.6 270 top
RM5  -  [R_0201]  25.58 144.8 180 top
RM6  -  [R_0201]  18.73 133.17 90 top
RM7  -  [R_0201]  25.45 161.89 270 top
RM9  -  [R_0201]  24.69 138.7 0 top
RM10  -  [R_0201]  17.63 161.05 0 bottom
RM11  -  [R_0402]  22.21 133.65 270 top
RM12  -  [R_0402]  25.58 139.46 180 top
RM13  -  [R_0402]  25.55 138.03 180 top
RM14  -  [R_0201]  25.45 134.38 180 top
RM15  -  [R0603_0OHM]  24.82 132.61 270 top
RM16  -  [R_0201]  23.56 134.32 90 top
RM17  -  [R_0201]  22.97 133.81 270 top
RM18  -  [R_0201]  24.19 134.9 270 top
RM19  -  [R_0402]  24.69 142.26 0 top
RM20  -  [R_0402]  23 131.62 90 top
RM21  -  [R_0201]  9.03 141.24 0 bottom
RM24  -  [R_0201]  15.74 138.57 180 top
RM25  -  [R_0201]  13.29 138.19 0 bottom
RM26  -  [R_0201]  14.48 139.02 270 bottom
RM27  -  [R_0402]  24.69 144.04 0 top
RM28  -  [R_0201]  25.45 159.95 270 top
RM102  -  [R_0201]  15.67 141.73 270 top
RM103  -  [R_0201]  15.65 139.88 90 top
RM1145  -  [R_0201]  95.66 76.66 180 top
RM1834  -  [R_0402]  14.93 140.41 90 top
RN1  -  [R_0201]  340.49 167.34 180 top
RN33  -  [R_0402]  337.11 171.29 270 top
RP1  -  [RP_0804_8P4R]  99.74 79.44 0 top
RP2  -  [RP_0804_8P4R]  63.99 81.54 0 top
RP4  -  [RP_0804_8P4R]  69.65 78.28 180 bottom
RP8  -  [RP_0804_8P4R]  69.21 80.93 180 top
RP15  -  [RP_0804_8P4R]  103.34 71.72 90 bottom
RP19  -  [RP_0804_8P4R]  283.2 78.01 180 top
RP20  -  [RP_0804_8P4R]  308.27 95.59 270 top
RP22  -  [RP_0804_8P4R]  68.49 86.38 0 top
RP23  -  [RP_0804_8P4R]  68.63 85.11 0 bottom
RR1  -  [R_0201]  343.75 102.13 180 bottom
RR2  -  [R0402_0OHM]  332.68 106.25 180 bottom
RR3  -  [R0402_0OHM]  332.68 107.14 180 bottom
RR4  -  [R0402_0OHM]  333.87 108.02 90 bottom
RR5  -  [R0402_0OHM]  336.47 109.1 90 bottom
RR6  -  [R_0402]  334.63 99.76 90 bottom
RR7  -  [R0402_0OHM]  337.36 109.1 90 bottom
RR8  -  [R0402_0OHM]  338.25 109.1 90 bottom
RR9  -  [R_0201]  343.17 102.89 0 bottom
RR10  -  [R0201_0OHM]  341.17 101.29 90 bottom
RR41  -  [R_0201]  340.21 111.55 90 bottom
RR42  -  [R_0201]  338 111.87 90 bottom
RR43  -  [R_0201]  342.44 111.55 90 bottom
RR44  -  [R_0201]  341.81 111.55 90 bottom
RR45  -  [R_0201]  338.63 111.87 90 bottom
RT1  -  [R_0402]  25.81 104.34 90 top
RT2  -  [R_0402]  27.61 108.86 0 top
RT3  -  [R_0201]  22.86 115.68 270 top
RT4  -  [R_0201]  32.73 110.38 180 bottom
RT5  -  [R_0402]  29.39 102.76 0 top
RT6  -  [R_0201]  32.37 109.57 180 top
RT7  -  [R_0201]  32.25 111.37 180 top
RT8  -  [R_0201]  32.25 110.8 180 top
RT9  -  [R_0201]  32.25 110.2 180 top
RT10  -  [R_0402]  22.78 108.22 0 top
RT12  -  [R_0201]  22.72 101.78 270 top
RT15  -  [R_0201]  38.81 90.76 90 top
RT16  -  [R_0201]  36.7 93.24 90 top
RT17  -  [R_0201]  39.84 98.44 0 top
RT18  -  [R_0201]  37.39 98.4 90 top
RT21  -  [R_0201]  29.45 115.25 270 top
RT22  -  [R_0201]  27.86 113.94 270 bottom
RT23  -  [R_0201]  27.76 114 0 top
RT25  -  [R_0201]  22.22 115.62 270 top
RT33  -  [R_0201]  30.78 112.73 180 top
RT34  -  [R_0201]  30.78 113.3 180 top
RT35  -  [R_0201]  25.1 113.91 270 bottom
RT36  -  [R_0201]  26.59 113.94 270 bottom
RT37  -  [R_0201]  27.23 113.94 270 bottom
RT38  -  [R_0201]  26.57 114.83 180 top
RT39  -  [R_0201]  16.97 116.85 270 bottom
RT40  -  [R_0201]  24.5 115.4 270 top
RT41  -  [R_0201]  31.56 111.8 90 bottom
RT42  -  [R_0201]  33.77 109.85 270 top
RT43  -  [R_0201]  27.14 113.94 180 top
RT44  -  [R_0201]  17.43 109.17 0 bottom
RT45  -  [R_0201]  17.43 109.78 0 bottom
RT46  -  [R_0603]  15.79 112.86 270 bottom
RT107  -  [R_0201]  31.37 112.73 90 top
RT113  -  [R0603_0OHM]  18.33 120.04 0 top
RT164  -  [R_0201]  22.15 101.2 90 top
RT167  -  [R_0201]  14.95 120.03 180 bottom
RT168  -  [R_0201]  19.61 119.78 90 bottom
RT169  -  [R_0201]  20.24 119.78 90 bottom
RT170  -  [R_0201]  23 126.46 0 top
RT171  -  [R_0201]  45.26 95.99 270 top
RT176  -  [R0201_0OHM]  22.95 129.08 90 bottom
RT177  -  [R0201_0OHM]  22.36 129.08 90 bottom
RT178  -  [R0201_0OHM]  15.54 122.38 180 bottom
RT181  -  [R0201_0OHM]  23.41 120.52 270 bottom
RT182  -  [R0201_0OHM]  23.16 122.45 0 top
RT183  -  [R_0201]  20.51 127.88 270 top
RT184  -  [R0201_0OHM]  17.13 129.94 270 bottom
RT185  -  [R0201_0OHM]  16.22 129.94 270 bottom
RT186  -  [R_0201]  25.03 123.46 0 top
RT187  -  [R_0201]  18.63 129.62 270 bottom
RT188  -  [R_0201]  18 129.62 270 bottom
RT189  -  [R_0201]  23.16 124.53 90 top
RT190  -  [R0402_0OHM]  16.43 124.86 180 bottom
RT191  -  [R_0402]  16.18 125.75 180 bottom
RT194  -  [R_0201]  24.22 121.81 180 top
RT195  -  [R0201_0OHM]  25.29 117.16 270 top
RT199  -  [R_0201]  25.12 124.86 0 top
RT200  -  [R0201_0OHM]  21.07 119.74 90 bottom
RT201  -  [R0201_0OHM]  21.64 119.74 90 bottom
RT202  -  [R_0201]  30.21 115.3 90 top
RT207  -  [R_0201]  17.43 110.36 0 bottom
RT208  -  [R_0201]  17.43 108.59 0 bottom
RT209  -  [R_0201]  23.95 113.48 180 bottom
RT226  -  [R_0201]  18.43 126.64 0 top
RT227  -  [R_0201]  22.62 127.02 0 top
RT232  -  [R_0201]  18.67 130.73 180 bottom
RT233  -  [R_0201]  19.81 129 180 bottom
RT241  -  [R0603_0OHM]  14.57 110.21 90 bottom
RT242  -  [R_0402]  33.1 109.57 270 top
RT243  -  [R0402_0OHM]  40.7 97.74 180 top
RT244  -  [R0201_0OHM]  29.45 116.45 270 top
RT245  -  [R_0201]  25.03 124.1 0 top
RT429  -  [R_0201]  21.45 123.89 90 top
RT430  -  [R_0201]  18.76 123.34 180 top
RT431  -  [R_0201]  17.75 127.12 270 top
RT432  -  [R_0201]  17.18 128.1 270 top
RT433  -  [R0201_0OHM]  18.85 114.95 0 top
RT435  -  [R_0201]  14.27 114.34 90 bottom
RT437  -  [R_0201]  25.03 122.83 0 top
RT1092  -  [R_0603]  20.81 122.31 270 top
RT1093  -  [R_0201]  20.5 129.09 270 top
RT1095  -  [R_0402]  14.4 121.19 0 bottom
RT1133  -  [R_0402]  171.88 76.85 0 top
RT1134  -  [R_0402]  23.53 115 90 top
RT1135  -  [R_0402]  294.72 95.92 270 top
RT1136  -  [R_0402]  69.57 75.02 180 bottom
RT1139  -  [R_0402]  308.1 84.47 180 top
RT1141  -  [R_0201]  19.69 131.32 90 bottom
RT1142  -  [R_0201]  20.73 131.32 90 bottom
RT1143  -  [R_0201]  20.5 133.11 270 bottom
RT1144  -  [R_0201]  19.91 133.11 270 bottom
RT1145  -  [R_0201]  22.78 114.06 270 bottom
RT5832  -  [R0201_0OHM]  17.03 107.28 0 bottom
RT5833  -  [R0201_0OHM]  17.03 106.72 0 bottom
RT5834  -  [R0201_0OHM]  17.48 102.06 0 bottom
RT5835  -  [R0201_0OHM]  17.48 102.63 0 bottom
RT5836  -  [R_0201]  16.56 123.97 0 bottom
RT5837  -  [R_0201]  16.56 123.41 0 bottom
RT5838  -  [R_0201]  16.51 122.24 90 bottom
RT5839  -  [R_0402]  309.55 84.35 0 top
RT5840  -  [R_0402]  309.55 83.58 0 top
RT5841  -  [R0201_0OHM]  23.56 117.86 270 top
RT5842  -  [R_0201]  16.99 118.43 270 bottom
RT5843  -  [R_0201]  70.89 71.9 180 top
RT5844  -  [R0201_0OHM]  25.43 125.68 0 bottom
RT5845  -  [R0201_0OHM]  32.28 111.02 180 bottom
RT5846  -  [R0201_0OHM]  26.42 115.4 180 top
RT5847  -  [R_0201]  27.76 113.43 0 top
RT5848  -  [R_0201]  27.76 112.86 0 top
RT5849  -  [R_0201]  69.74 71.33 0 top
RT5850  -  [R_0201]  16.97 114.98 90 bottom
RT5855  -  [R_0201]  14.21 112.44 90 bottom
RT5856  -  [R_0201]  304.43 91.2 0 top
RT5857  -  [R_0201]  86.92 72.24 90 top
RV8  -  [R_0402]  248.89 123.31 0 top
RV11  -  [R_0402]  246.23 112.67 0 top
RV12  -  [R_0402]  251.71 119.02 180 top
RV103  -  [R_0402]  218.03 183.66 0 top
RV107  -  [R_0402]  45.47 95.9 180 bottom
RV109  -  [R_0402]  42.65 95.9 0 bottom
RV110  -  [R0402_0OHM]  46.91 95.4 90 bottom
RV111  -  [R_0402]  252.02 112.54 180 top
RV112  -  [R_0402]  220.6 183.66 180 top
RV113  -  [R0201_0OHM]  48.31 95.9 180 bottom
RV114  -  [R_0402]  49.2 95.9 270 bottom
RV119  -  [R_0402]  39.17 100.91 90 top
RV120  -  [R_0402]  38.28 101.82 270 top
RV135  -  [R_0402]  34.12 101.34 270 top
RV325  -  [R_0402]  198.08 116.06 270 top
RV326  -  [R_0402]  198.88 116.06 270 top
RV399  -  [R_0402]  244.6 115.65 270 top
RV520  -  [R0201_0OHM]  60.38 95.61 90 bottom
RV521  -  [R0201_0OHM]  61.01 95.61 90 bottom
RV522  -  [R0201_0OHM]  62.66 95.61 90 bottom
RV523  -  [R0201_0OHM]  63.3 95.61 90 bottom
RV524  -  [R0201_0OHM]  63.93 95.61 90 bottom
RV525  -  [R0201_0OHM]  64.57 95.61 90 bottom
RV526  -  [R0201_0OHM]  65.33 95.61 90 bottom
RV527  -  [R0201_0OHM]  65.96 95.61 90 bottom
RV528  -  [R0201_0OHM]  59.74 95.61 90 bottom
RV529  -  [R0201_0OHM]  59.11 95.61 90 bottom
RV530  -  [R_0201]  15.46 151.02 180 top
RV531  -  [R_0201]  15.46 151.66 180 top
RV532  -  [R_0201]  15.46 155.16 180 top
RV533  -  [R_0201]  15.46 154.58 180 top
RV534  -  [R_0201]  14.57 153.35 180 top
RV535  -  [R_0201]  14.57 152.76 180 top
RV536  -  [R_0201]  14.57 149.75 180 top
RV537  -  [R_0201]  14.57 149.12 180 top
RV538  -  [R_0201]  14.27 151.57 270 top
RV539  -  [R_0201]  14.27 155.16 270 top
RV540  -  [R_0201]  13.39 153.35 270 top
RV541  -  [R_0201]  13.39 149.79 270 top
RV550  -  [R_0402]  205.49 112.41 180 top
RV551  -  [R_0402]  212.98 112.57 90 top
RV552  -  [R_0402]  195.81 120.48 0 bottom
RV553  -  [R_0402]  210.24 122.4 270 bottom
RV554  -  [R_0402]  212.27 116.74 270 top
RV557  -  [R_0402]  219.51 117.12 270 top
RV561  -  [R_0402]  24.69 143.15 0 top
RV562  -  [R_0402]  205.28 114.11 90 top
RV563  -  [R_0402]  220.13 114.89 0 top
RV564  -  [R_0402]  212.23 114.94 0 top
RV566  -  [R_0402]  209.98 109.42 90 top
RV567  -  [R_0402]  211.51 122.4 270 bottom
RV570  -  [R_0402]  198.68 119.6 270 top
RV571  -  [R_0402]  199.44 119.6 270 top
RV572  -  [R_0402]  207.07 122.72 270 bottom
RV573  -  [R_0402]  206.18 122.72 270 bottom
RV574  -  [R_0402]  211.21 148.04 90 top
RV575  -  [R_0402]  201.89 129.71 270 top
RV576  -  [R_0402]  201.09 129.7 270 top
RV577  -  [R_0402]  187.65 128.33 0 bottom
RV578  -  [R_0402]  188.96 153 270 bottom
RV579  -  [R_0402]  218.41 119.53 0 top
RV580  -  [R_0402]  225.23 109.94 180 top
RV581  -  [R_0402]  218.55 117.12 270 top
RV582  -  [R_0402]  197.03 128.52 0 top
RV587  -  [R_0402]  222.43 108.92 180 top
RV589  -  [R_0402]  186.79 128.33 90 bottom
RV590  -  [R_0402]  195.36 115.28 270 top
RV591  -  [R_0402]  198.17 116.99 90 top
RV592  -  [R_0402]  188.56 129.22 180 bottom
RV593  -  [R_0402]  186.88 130.93 0 bottom
RV594  -  [R_0402]  217.22 113.25 270 top
RV597  -  [R_0603]  196.79 132.03 315 top
RV600  -  [R_0402]  212.94 150.83 270 top
RV601  -  [R_0402]  214.6 150.02 180 top
RV602  -  [R_0402]  217.02 144.18 180 top
RV605  -  [R_0402]  229.11 170.77 180 top
RV606  -  [R_0402]  241.87 129.49 90 top
RV607  -  [R_0402]  209.4 172.23 0 top
RV608  -  [R_0402]  243.4 146.77 180 top
RV613  -  [R_0402]  215.32 171.07 90 bottom
RV614  -  [R_0402]  223.01 170.24 90 bottom
RV615  -  [R_0402]  241.22 149.36 90 top
RV616  -  [R_0402]  239.57 130.65 270 top
RV617  -  [R_0402]  223.01 172.83 270 bottom
RV618  -  [R_0402]  213.36 172.22 90 top
RV619  -  [R_0402]  237.11 170.07 180 top
RV620  -  [R_0402]  205.4 171.66 0 top
RV621  -  [R_0201]  236.32 170.96 0 top
RV622  -  [R_0201]  236.32 171.72 0 top
RV623  -  [R_0402]  222.94 175.6 180 top
RV624  -  [R_0402]  221.37 174.65 0 top
RV625  -  [R_0402]  221.46 176.44 90 top
RV626  -  [R_0201]  202.95 171.72 180 top
RV627  -  [R_0201]  202.95 170.96 180 top
RV628  -  [R_0201]  242.1 123.26 270 top
RV629  -  [R_0201]  241.53 123.26 270 top
RV630  -  [R_0201]  239.28 144.67 0 bottom
RV631  -  [R_0402]  240.46 134.37 90 top
RV632  -  [R_0402]  242.74 155.35 90 top
RV633  -  [R_0402]  239.65 122.4 270 top
RV634  -  [R_0402]  242.99 163.53 0 top
RV635  -  [R_0402]  243.91 161.68 90 top
RV636  -  [R_0402]  244.82 161.63 0 top
RV637  -  [R_0201]  241 156.77 90 top
RV638  -  [R_0201]  240.42 156.77 90 top
RV639  -  [R_0402]  223.2 117.13 270 top
RV640  -  [R_0402]  224.21 117.13 270 top
RV641  -  [R_0402]  228.71 118.5 90 top
RV642  -  [R_0402]  223.2 119.42 270 top
RV643  -  [R_0402]  224.21 119.42 270 top
RV644  -  [R_0402]  227.77 119.42 270 top
RV645  -  [R_0402]  221.23 117.13 270 top
RV646  -  [R_0402]  225.99 117.13 270 top
RV647  -  [R_0402]  225.1 117.13 270 top
RV648  -  [R_0402]  226.88 117.13 270 top
RV649  -  [R_0402]  222.18 117.13 270 top
RV650  -  [R_0402]  220.33 117.12 270 top
RV651  -  [R_0402]  221.21 119.41 270 top
RV652  -  [R_0402]  225.99 119.42 270 top
RV653  -  [R_0402]  225.1 119.42 270 top
RV654  -  [R_0402]  226.88 119.42 270 top
RV655  -  [R_0402]  222.18 119.42 270 top
RV656  -  [R_0402]  220.21 119.55 270 top
RV657  -  [R_0402]  245.52 114.75 90 top
RV658  -  [R_0603]  202.22 111.16 135 top
RV1068  -  [R_0603]  199.39 134.63 270 top
RV1080  -  [R_0402]  229.67 118.5 90 top
RV1082  -  [R_0402]  216.2 113.25 270 top
RV1083  -  [R_0402]  214.1 112.29 0 top
RV1084  -  [R_0402]  217.22 109.82 270 top
RV1086  -  [R_0402]  226.76 113.84 270 top
RV1095  -  [R_0201]  162.07 185.27 180 bottom
RV1098  -  [R_0201]  181.98 179.86 0 bottom
RV1112  -  [R_0402]  242.43 113.3 180 top
RV1128  -  [R_0402]  172.93 177.97 0 top
RV1130  -  [R_0402]  162.32 181.48 180 top
RV1131  -  [R_0402]  198.77 110.09 0 top
RV1132  -  [R_0402]  197.89 110.09 180 top
RV1133  -  [R_0402]  240.13 110.13 180 top
RV1350  -  [R_0402]  246.56 118.81 90 top
RV1807  -  [R_0402]  173.09 179.65 270 top
RV1808  -  [R_0402]  222.35 185.76 90 top
RV1809  -  [R_0402]  163.31 186.21 270 top
RV1810  -  [R_0402]  166.74 186.21 270 top
RV1811  -  [R_0402]  252.4 108.86 180 top
RV1833  -  [R_0402]  216.03 119.27 180 top
RV1834  -  [R_0402]  196.98 119.53 0 top
RV1835  -  [R_0402]  183.79 180.62 180 bottom
RV1836  -  [R_0402]  184.4 183.41 180 top
RV1837  -  [R_0402]  213.41 122.45 270 bottom
RV1838  -  [R_0402]  210.32 114.93 0 top
RV1839  -  [R_0402]  211.63 112.21 90 top
RV1840  -  [R_0402]  207.85 121.79 90 bottom
RV1841  -  [R_0402]  196.24 119.53 180 top
RV1842  -  [R_0402]  219.63 112.74 270 top
RV1843  -  [R0201_0OHM]  64.54 100.65 180 top
RV1844  -  [R_0402]  201.85 114.78 270 top
RZ18  -  [R0603_0OHM]  55.17 70.12 0 top
RZ28  -  [R0603_0OHM]  346.19 103.7 180 bottom
RZ32  -  [R_0402]  192.71 74.27 270 top
RZ37  -  [R0603_0OHM]  50.34 94.54 90 bottom
RZ38  -  [R_0402]  76.7 69.12 270 bottom
RZ39  -  [R_0402]  337.11 129.05 270 bottom
RZ40  -  [R_0402]  61.14 95.06 90 top
RZ41  -  [R_0402]  286 88.92 180 top
RZ43  -  [R_0402]  261.92 106.41 270 top
RZ46  -  [R_0402]  56.31 75.58 180 top
RZ50  -  [R_0201]  106.6 112.68 270 top
RZ58  -  [R0201_0OHM]  105.65 112.1 90 top
RZ59  -  [R_0402]  109.7 121.43 0 top
RZ60  -  [R0402_0OHM]  111.84 116.59 0 top
RZ61  -  [R_0402]  117.86 118.01 90 top
RZ71  -  [R_0402]  112.81 117.4 90 top
RZ72  -  [R_0402]  187.96 109.49 180 top
RZ81  -  [R_0402]  120.4 123.97 180 top
RZ82  -  [R_0402]  118.59 127.91 0 top
RZ84  -  [R_0402]  117.02 126.21 270 top
RZ86  -  [R_0402]  111.79 117.4 90 top
RZ87  -  [R_0402]  125.78 126.21 270 top
RZ91  -  [R0402_0OHM]  103.1 121.68 0 top
RZ106  -  [R_0402]  249.38 108.73 0 top
RZ1133  -  [R_0402]  56.31 74.82 180 top
RZ1136  -  [R0603_0OHM]  311.39 80.74 180 top
RZ1138  -  [R0603_0OHM]  163.13 75.68 180 top
RZ1141  -  [R_0402]  331.06 112.54 0 bottom
RZ1142  -  [R_0402]  334.14 113.18 180 bottom
RZ1148  -  [R0603_0OHM]  273.16 70.88 0 top
RZ1149  -  [R_0402]  77.77 72.87 270 top
RZ1150  -  [R_0201]  18.61 118.75 270 top
RZ1151  -  [R_0201]  173.48 72.15 0 top
RZ1153  -  [R_0402]  104.7 115.66 270 top
RZ1951  -  [R_0402]  243.4 78.02 180 top
RZ1952  -  [R_0402]  125.75 80.67 90 top
RZ1953  -  [R_0201]  107.49 112.12 90 top
RZ1954  -  [R_0402]  104.01 122.57 180 top
RZ1955  -  [R_0402]  118.16 125.16 90 bottom
RZ1956  -  [R_0402]  232.46 71.57 90 top
RZ1957  -  [R_0402]  119.05 125.16 90 bottom
RZ1958  -  [R_0402]  236.46 71.51 90 top
RZ1960  -  [R0603_0OHM]  318.25 93.62 180 bottom
RZ1964  -  [R_0402]  244.78 119.73 270 top
RZ1965  -  [R_0402]  104.7 116.46 90 top
RZ1966  -  [R_0402]  125.78 128.11 270 top
SW1  -  [SW_SKRBAAE010_4P]  334.3 181.44 90 top
SW2  -  [SW_NTC311-EA1T-A160T_4P]  346.39 177.52 90 top
SW4  -  [SW_SSAL120100_3P]  111.76 71.46 0 top
SW_BOT  -  [SW_SKRBAAE010_4P]  327.16 97.18 0 bottom
T2  -  [TPC12]  78.68 78.2 0 top
T4  -  [TPC12]  64.97 87.93 180 bottom
T8  -  [TPC12]  66.28 83.7 180 bottom
T17  -  [TPC12]  79.74 69.35 180 bottom
